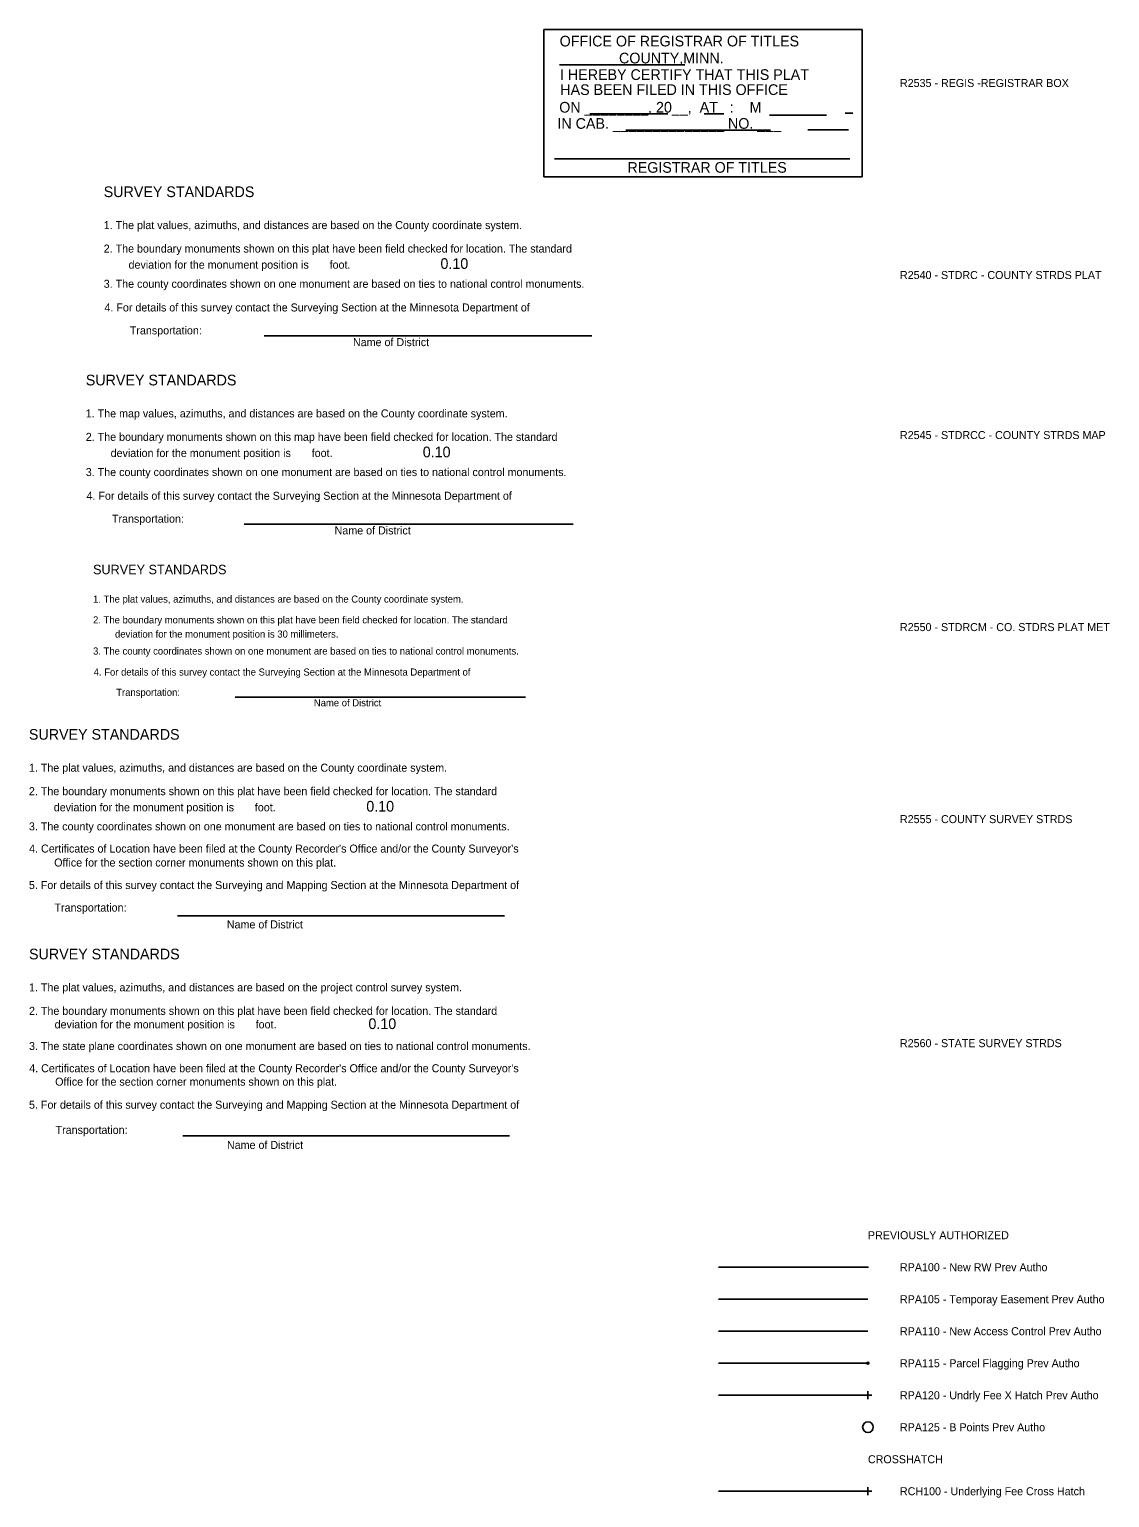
# Model space of a CAD drawing. Extents: x 2147716 to 2176321, y 2125040 to 2131750.
# Drawn here: x 2169680 to 2170692, y 2126938 to 2128314 of the extents above; entities that cross this region are included whole.
import ezdxf

# ---------------------------------------------------------------- set-up
doc = ezdxf.new("R2010")
doc.units = 0
for name, color, linetype in [('ACC PREV AUTH', 7, 'Continuous'), ('B PNTS PREV AUTH', 7, 'Continuous'), ('Default', 7, 'Continuous'), ('NRW PREV AUTH', 7, 'Continuous'), ('PAR FLAG PREV AUTH', 7, 'Continuous'), ('PLAT INFO', 7, 'Continuous'), ('TMP ESMT PREV AUTH', 7, 'Continuous'), ('UNDRLY FEE', 7, 'Continuous'), ('UNDRLY FEE PREV AUTH', 7, 'Continuous')]:
    doc.layers.add(name, color=color, linetype=linetype)

msp = doc.modelspace()

# ---------------------------------------------------------------- linework, layer by layer
at = {"layer": 'ACC PREV AUTH'}
msp.add_line((2170465.6, 2127094), (2170325.6, 2127094), dxfattribs=at)
at = {"layer": 'B PNTS PREV AUTH'}
msp.add_circle((2170465.6, 2127004), 5, dxfattribs=at)
at = {"layer": 'Default'}
for p, q in [((2170469.4, 2127034), (2170461.9, 2127034)), ((2170465.6, 2127037.7), (2170465.6, 2127030.2)), ((2170469.4, 2126944), (2170461.9, 2126944)), ((2170465.6, 2126947.7), (2170465.6, 2126940.2))]:
    msp.add_line(p, q, dxfattribs=at)
at = {"layer": 'NRW PREV AUTH'}
for p, q in [((2170465.6, 2127154), (2170325.6, 2127154)), ((2170465.5, 2127153.8), (2170465.7, 2127154.2)), ((2170465.5, 2127154.2), (2170465.7, 2127153.8))]:
    msp.add_line(p, q, dxfattribs=at)
at = {"layer": 'PAR FLAG PREV AUTH'}
msp.add_line((2170465.6, 2127064), (2170325.6, 2127064), dxfattribs=at)
msp.add_circle((2170465.6, 2127064), 1, dxfattribs=at)
at = {"layer": 'PLAT INFO'}
for p, q in [((2170162, 2128176.1), (2170161.9, 2128314.2)), ((2170161.9, 2128314.2), (2170460.1, 2128314.2)), ((2170460.1, 2128176.1), (2170460.1, 2128314.2)), ((2170176.6, 2128280.9), (2170294.1, 2128280.9)), ((2170278, 2128235.1), (2170205.1, 2128235.1)), ((2170312, 2128234.9), (2170330.7, 2128234.9)), ((2170373.5, 2128233.7), (2170426.7, 2128233.7)), ((2170451.5, 2128235.8), (2170444.2, 2128235.8)), ((2170238.7, 2128219.6), (2170374.3, 2128219.6)), ((2170409.2, 2128219.9), (2170447.5, 2128219.9)), ((2170171.8, 2128192.8), (2170448.6, 2128192.8)), ((2170162, 2128176.1), (2170460.1, 2128176.1)), ((2169899.8, 2128026.8), (2170206.8, 2128026.8)), ((2169880.9, 2127850.3), (2170189.2, 2127850.3)), ((2169872.6, 2127688.2), (2170144.6, 2127688.2)), ((2169818.4, 2127483.4), (2170125, 2127483.4)), ((2169823.4, 2127277.1), (2170129.8, 2127277.1))]:
    msp.add_line(p, q, dxfattribs=at)
at = {"layer": 'TMP ESMT PREV AUTH'}
msp.add_line((2170465.6, 2127124), (2170325.6, 2127124), dxfattribs=at)
at = {"layer": 'UNDRLY FEE'}
msp.add_line((2170465.6, 2126944), (2170325.6, 2126944), dxfattribs=at)
at = {"layer": 'UNDRLY FEE PREV AUTH'}
msp.add_line((2170465.6, 2127034), (2170325.6, 2127034), dxfattribs=at)

# ---------------------------------------------------------------- texts
at = {"layer": 'Default'}
for s, p in [('R2535 - REGIS -REGISTRAR BOX', (2170495.6, 2128260.2)), ('R2540 - STDRC - COUNTY STRDS PLAT', (2170495.6, 2128080.2)), ('R2545 - STDRCC - COUNTY STRDS MAP', (2170495.6, 2127930.2)), ('R2550 - STDRCM - CO. STDRS PLAT MET', (2170495.6, 2127750.2)), ('R2555 - COUNTY SURVEY STRDS', (2170495.6, 2127570.2)), ('R2560 - STATE SURVEY STRDS', (2170495.6, 2127360.2)), ('PREVIOUSLY AUTHORIZED', (2170465.6, 2127180.2)), ('RPA100 - New RW Prev Autho', (2170495.6, 2127150.2)), ('RPA105 - Temporay Easement Prev Autho', (2170495.6, 2127120.2)), ('RPA110 - New Access Control Prev Autho', (2170495.6, 2127090.2)), ('RPA125 - B Points Prev Autho', (2170495.6, 2127000.2)), ('CROSSHATCH', (2170465.6, 2126970.2)), ('RCH100 - Underlying Fee Cross Hatch', (2170495.6, 2126940.2))]:
    msp.add_text(s, height=7.5, dxfattribs=at).set_placement(p)
at = {"layer": 'PAR FLAG PREV AUTH'}
for s, p in [('RPA115 - Parcel Flagging Prev Autho', (2170495.6, 2127060.2)), ('RPA120 - Undrly Fee X Hatch Prev Autho', (2170495.6, 2127030.2))]:
    msp.add_text(s, height=7.5, dxfattribs=at).set_placement(p)
at = {"layer": 'PLAT INFO'}
for s, p in [('OFFICE OF REGISTRAR OF TITLES ', (2170176.7, 2128298.2)), ('               COUNTY,MINN.', (2170176.6, 2128282.3)), ('I HEREBY CERTIFY THAT THIS PLAT', (2170177, 2128266.8)), ('HAS BEEN FILED IN THIS OFFICE', (2170177.3, 2128252.7)), ('ON ________, 20__,  AT   :    M', (2170176.3, 2128236.2)), ('IN CAB. ______________ NO. ___', (2170174.6, 2128221)), ('REGISTRAR OF TITLES', (2170240.2, 2128179.8))]:
    msp.add_text(s, height=10, rotation=0.0124, dxfattribs=at).set_placement(p)
for s, height, p in [('SURVEY STANDARDS', 10, (2169749.4, 2128157)), ('1. The plat values, azimuths, and distances are based on the County coordinate system.', 7.5, (2169749.4, 2128127)), ('2. The boundary monuments shown on this plat have been field checked for location. The standard', 7.5, (2169749.4, 2128105)), ('0.10', 10, (2170065, 2128089.7)), ('deviation for the monument position is       foot.', 7.5, (2169772.7, 2128089.9)), ('3. The county coordinates shown on one monument are based on ties to national control monuments.', 7.5, (2169749.4, 2128072)), ('4. For details of this survey contact the Surveying Section at the Minnesota Department of', 7.5, (2169750.1, 2128049.8)), ('Transportation:', 7.5, (2169773.9, 2128028.3)), ('Name of District', 7.5, (2169983, 2128017.3)), ('SURVEY STANDARDS', 10, (2169732.6, 2127980.5)), ('1. The map values, azimuths, and distances are based on the County coordinate system.', 7.5, (2169732.6, 2127950.5)), ('2. The boundary monuments shown on this map have been field checked for location. The standard', 7.5, (2169732.6, 2127928.5)), ('deviation for the monument position is       foot.', 7.5, (2169755.9, 2127913.4)), ('0.10', 10, (2170048.4, 2127913.1)), ('3. The county coordinates shown on one monument are based on ties to national control monuments.', 7.5, (2169732.6, 2127895.5)), ('4. For details of this survey contact the Surveying Section at the Minnesota Department of', 7.5, (2169733.3, 2127873.3)), ('Transportation:', 7.5, (2169757.1, 2127851.8)), ('Name of District', 7.5, (2169965.8, 2127840.8)), ('SURVEY STANDARDS', 8.858, (2169739.4, 2127803.5)), ('1. The plat values, azimuths, and distances are based on the County coordinate system.', 6.644, (2169739.4, 2127776.9)), ('2. The boundary monuments shown on this plat have been field checked for location. The standard', 6.644, (2169739.4, 2127757.4)), ('deviation for the monument position is 30 millimeters.', 6.644, (2169760, 2127744.1)), ('3. The county coordinates shown on one monument are based on ties to national control monuments.', 6.644, (2169739.4, 2127728.2)), ('4. For details of this survey contact the Surveying Section at the Minnesota Department of', 6.644, (2169740, 2127708.5)), ('Transportation:', 6.644, (2169761.1, 2127689.5)), ('Name of District', 6.644, (2169946.3, 2127679.7)), ('SURVEY STANDARDS', 10, (2169679.3, 2127648.4)), ('1. The plat values, azimuths, and distances are based on the County coordinate system.', 7.5, (2169679.3, 2127618.4)), ('2. The boundary monuments shown on this plat have been field checked for location. The standard', 7.5, (2169679.3, 2127596.4)), ('0.10', 10, (2169995.5, 2127581)), ('deviation for the monument position is       foot.', 7.5, (2169702.6, 2127581.3)), ('3. The county coordinates shown on one monument are based on ties to national control monuments.', 7.5, (2169679.3, 2127563.4)), ("4. Certificates of Location have been filed at the County Recorder's Office and/or the County Surveyor's", 7.5, (2169679.5, 2127542.6)), ('Office for the section corner monuments shown on this plat.', 7.5, (2169703, 2127529.5)), ('5. For details of this survey contact the Surveying and Mapping Section at the Minnesota Department of', 7.5, (2169679.3, 2127508.4)), ('Transportation:', 7.5, (2169703.3, 2127487.3)), ('Name of District', 7.5, (2169864.8, 2127471.5)), ('SURVEY STANDARDS', 10, (2169679.4, 2127442.5)), ('1. The plat values, azimuths, and distances are based on the project control survey system.', 7.5, (2169679.4, 2127412.5)), ('2. The boundary monuments shown on this plat have been field checked for location. The standard', 7.5, (2169679.4, 2127390.5)), ('deviation for the monument position is       foot.', 7.5, (2169703.4, 2127377.8)), ('0.10', 10, (2169997.5, 2127377.2)), ('3. The state plane coordinates shown on one monument are based on ties to national control monuments.', 7.5, (2169679.4, 2127357.5)), ("4. Certificates of Location have been filed at the County Recorder's Office and/or the County Surveyor's", 7.5, (2169679.6, 2127336.7)), ('Office for the section corner monuments shown on this plat.', 7.5, (2169703.9, 2127324.1)), ('5. For details of this survey contact the Surveying and Mapping Section at the Minnesota Department of', 7.5, (2169679.4, 2127302.5)), ('Transportation:', 7.5, (2169704.3, 2127278.9)), ('Name of District', 7.5, (2169864.9, 2127264.8))]:
    msp.add_text(s, height=height, dxfattribs=at).set_placement(p)

doc.saveas('drawing.dxf')
